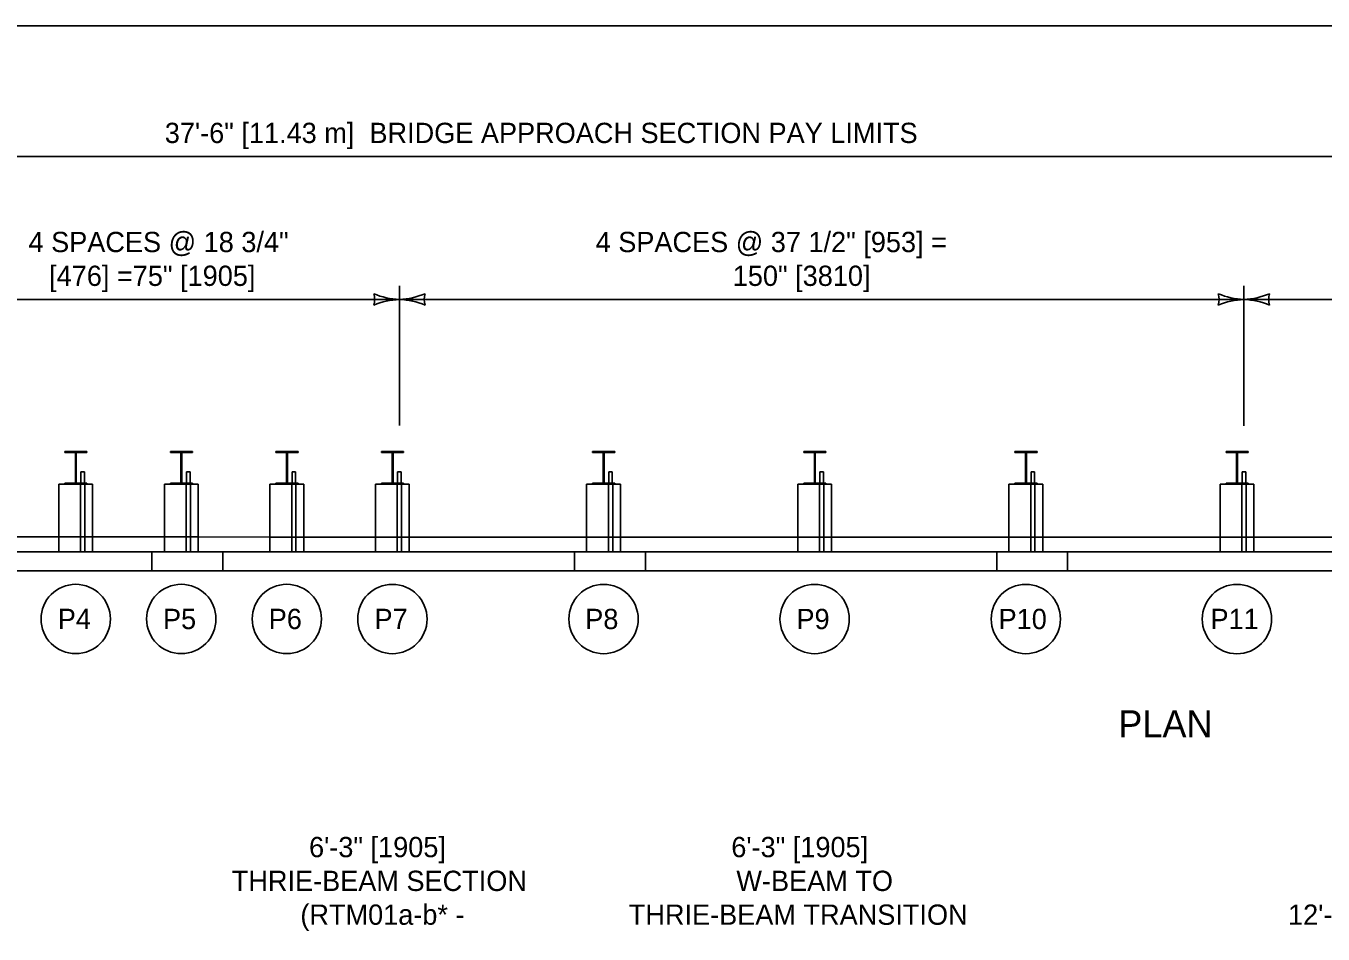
# Model space of a CAD drawing. Extents: x 49991 to 50160, y 49948 to 50051.
# Drawn here: x 50002.716 to 50006.556, y 49996.312 to 49998.999 of the extents above; entities that cross this region are included whole.
import ezdxf

# ---------------------------------------------------------------- set-up
doc = ezdxf.new("R2010")
doc.units = 0
for name, color, linetype in [('Level 1', 7, 'Continuous'), ('Level 2', 7, 'Continuous'), ('Level 3', 7, 'Continuous'), ('Level 4', 7, 'Continuous')]:
    doc.layers.add(name, color=color, linetype=linetype)

msp = doc.modelspace()

# ---------------------------------------------------------------- linework, layer by layer
at = {"layer": 'Level 1'}
for p, q in [((50002.8966, 49997.7403), (50002.831, 49997.7403)), ((50002.831, 49997.7403), (50002.831, 49997.7371)), ((50002.8966, 49997.7371), (50002.831, 49997.7371)), ((50002.8624, 49997.7371), (50002.8624, 49997.6464)), ((50002.8652, 49997.7371), (50002.8652, 49997.6464)), ((50002.8966, 49997.7371), (50002.8966, 49997.7403)), ((50003.2091, 49997.7403), (50003.1435, 49997.7403)), ((50003.1435, 49997.7403), (50003.1435, 49997.7371)), ((50003.2091, 49997.7371), (50003.1435, 49997.7371)), ((50003.1749, 49997.7371), (50003.1749, 49997.6464)), ((50003.1777, 49997.7371), (50003.1777, 49997.6464)), ((50003.2091, 49997.7371), (50003.2091, 49997.7403)), ((50003.5216, 49997.7403), (50003.456, 49997.7403)), ((50003.456, 49997.7403), (50003.456, 49997.737)), ((50003.5216, 49997.737), (50003.456, 49997.737)), ((50003.4874, 49997.737), (50003.4874, 49997.6463)), ((50003.4902, 49997.737), (50003.4902, 49997.6463)), ((50003.5216, 49997.737), (50003.5216, 49997.7403)), ((50003.8341, 49997.7403), (50003.7685, 49997.7403)), ((50003.7685, 49997.7403), (50003.7685, 49997.737)), ((50003.8341, 49997.737), (50003.7685, 49997.737)), ((50003.7999, 49997.737), (50003.7999, 49997.6463)), ((50003.8027, 49997.737), (50003.8027, 49997.6463)), ((50003.8341, 49997.737), (50003.8341, 49997.7403)), ((50004.4591, 49997.7402), (50004.3935, 49997.7402)), ((50004.3935, 49997.7402), (50004.3935, 49997.737)), ((50004.4591, 49997.737), (50004.3935, 49997.737)), ((50004.4249, 49997.737), (50004.4249, 49997.6463)), ((50004.4277, 49997.737), (50004.4277, 49997.6463)), ((50004.4591, 49997.737), (50004.4591, 49997.7402)), ((50005.0841, 49997.7402), (50005.0185, 49997.7402)), ((50005.0185, 49997.7402), (50005.0185, 49997.737)), ((50005.0841, 49997.737), (50005.0185, 49997.737)), ((50005.0499, 49997.737), (50005.0499, 49997.6463)), ((50005.0527, 49997.737), (50005.0527, 49997.6463)), ((50005.0841, 49997.737), (50005.0841, 49997.7402)), ((50005.7091, 49997.7402), (50005.6435, 49997.7402)), ((50005.6435, 49997.7402), (50005.6435, 49997.737)), ((50005.7091, 49997.737), (50005.6435, 49997.737)), ((50005.6749, 49997.737), (50005.6749, 49997.6463)), ((50005.6777, 49997.737), (50005.6777, 49997.6463)), ((50005.7091, 49997.737), (50005.7091, 49997.7402)), ((50006.3341, 49997.7402), (50006.2685, 49997.7402)), ((50006.2685, 49997.7402), (50006.2685, 49997.7369)), ((50006.3341, 49997.7369), (50006.2685, 49997.7369)), ((50006.2999, 49997.7369), (50006.2999, 49997.6462)), ((50006.3027, 49997.7369), (50006.3027, 49997.6462)), ((50006.3341, 49997.7369), (50006.3341, 49997.7402)), ((50002.8789, 49997.6797), (50002.8894, 49997.6797)), ((50002.8789, 49997.6464), (50002.8789, 49997.6797)), ((50002.8894, 49997.6464), (50002.8894, 49997.6797)), ((50003.1914, 49997.6797), (50003.2019, 49997.6797)), ((50003.1914, 49997.6464), (50003.1914, 49997.6797)), ((50003.2019, 49997.6464), (50003.2019, 49997.6797)), ((50003.5039, 49997.6797), (50003.5144, 49997.6797)), ((50003.5039, 49997.6463), (50003.5039, 49997.6797)), ((50003.5144, 49997.6463), (50003.5144, 49997.6797)), ((50003.8164, 49997.6797), (50003.8269, 49997.6797)), ((50003.8164, 49997.6463), (50003.8164, 49997.6797)), ((50003.8269, 49997.6463), (50003.8269, 49997.6797)), ((50004.4414, 49997.6796), (50004.4519, 49997.6796)), ((50004.4414, 49997.6463), (50004.4414, 49997.6796)), ((50004.4519, 49997.6463), (50004.4519, 49997.6796)), ((50005.0664, 49997.6796), (50005.0769, 49997.6796)), ((50005.0664, 49997.6463), (50005.0664, 49997.6796)), ((50005.0769, 49997.6463), (50005.0769, 49997.6796)), ((50005.6914, 49997.6796), (50005.7019, 49997.6796)), ((50005.6914, 49997.6463), (50005.6914, 49997.6796)), ((50005.7019, 49997.6463), (50005.7019, 49997.6796)), ((50006.3164, 49997.6796), (50006.3269, 49997.6796)), ((50006.3164, 49997.6462), (50006.3164, 49997.6796)), ((50006.3269, 49997.6462), (50006.3269, 49997.6796)), ((50002.8133, 49997.6431), (50002.8133, 49997.4431)), ((50002.9133, 49997.6431), (50002.8133, 49997.6431)), ((50002.831, 49997.6431), (50002.831, 49997.6464)), ((50002.831, 49997.6464), (50002.8966, 49997.6464)), ((50002.831, 49997.6431), (50002.8966, 49997.6431)), ((50002.8966, 49997.6464), (50002.8966, 49997.6431)), ((50002.9133, 49997.4431), (50002.9133, 49997.6431)), ((50003.1258, 49997.6431), (50003.1258, 49997.4431)), ((50003.2258, 49997.6431), (50003.1258, 49997.6431)), ((50003.1435, 49997.6431), (50003.1435, 49997.6464)), ((50003.1435, 49997.6464), (50003.2091, 49997.6464)), ((50003.1435, 49997.6431), (50003.2091, 49997.6431)), ((50003.2091, 49997.6464), (50003.2091, 49997.6431)), ((50003.2258, 49997.4431), (50003.2258, 49997.6431)), ((50003.4383, 49997.6431), (50003.4383, 49997.4431)), ((50003.5383, 49997.6431), (50003.4383, 49997.6431)), ((50003.456, 49997.6431), (50003.456, 49997.6463)), ((50003.456, 49997.6463), (50003.5216, 49997.6463)), ((50003.456, 49997.6431), (50003.5216, 49997.6431)), ((50003.5216, 49997.6463), (50003.5216, 49997.6431)), ((50003.5383, 49997.4431), (50003.5383, 49997.6431)), ((50003.7508, 49997.6431), (50003.7508, 49997.4431)), ((50003.8508, 49997.6431), (50003.7508, 49997.6431)), ((50003.7685, 49997.6431), (50003.7685, 49997.6463)), ((50003.7685, 49997.6463), (50003.8341, 49997.6463)), ((50003.7685, 49997.6431), (50003.8341, 49997.6431)), ((50003.8341, 49997.6463), (50003.8341, 49997.6431)), ((50003.8508, 49997.4431), (50003.8508, 49997.6431)), ((50004.3758, 49997.6431), (50004.3758, 49997.4431)), ((50004.4758, 49997.6431), (50004.3758, 49997.6431)), ((50004.3935, 49997.6431), (50004.3935, 49997.6463)), ((50004.3935, 49997.6463), (50004.4591, 49997.6463)), ((50004.3935, 49997.6431), (50004.4591, 49997.6431)), ((50004.4591, 49997.6463), (50004.4591, 49997.6431)), ((50004.4758, 49997.4431), (50004.4758, 49997.6431)), ((50005.0008, 49997.643), (50005.0008, 49997.443)), ((50005.1008, 49997.643), (50005.0008, 49997.643)), ((50005.0185, 49997.643), (50005.0185, 49997.6463)), ((50005.0185, 49997.6463), (50005.0841, 49997.6463)), ((50005.0185, 49997.643), (50005.0841, 49997.643)), ((50005.0841, 49997.6463), (50005.0841, 49997.643)), ((50005.1008, 49997.443), (50005.1008, 49997.643)), ((50005.6258, 49997.643), (50005.6258, 49997.443)), ((50005.7258, 49997.643), (50005.6258, 49997.643)), ((50005.6435, 49997.643), (50005.6435, 49997.6463)), ((50005.6435, 49997.6463), (50005.7091, 49997.6463)), ((50005.6435, 49997.643), (50005.7091, 49997.643)), ((50005.7091, 49997.6463), (50005.7091, 49997.643)), ((50005.7258, 49997.443), (50005.7258, 49997.643)), ((50006.2508, 49997.643), (50006.2508, 49997.443)), ((50006.3508, 49997.643), (50006.2508, 49997.643)), ((50006.2685, 49997.643), (50006.2685, 49997.6462)), ((50006.2685, 49997.6462), (50006.3341, 49997.6462)), ((50006.2685, 49997.643), (50006.3341, 49997.643)), ((50006.3341, 49997.6462), (50006.3341, 49997.643)), ((50006.3508, 49997.443), (50006.3508, 49997.643)), ((50002.6008, 49997.487), (50002.8133, 49997.487)), ((50002.9133, 49997.487), (50003.1258, 49997.487)), ((50003.2258, 49997.487), (50003.4383, 49997.4869)), ((50003.5383, 49997.4869), (50003.7508, 49997.4869)), ((50003.8508, 49997.4869), (50004.3758, 49997.4869)), ((50004.4758, 49997.4869), (50005.0008, 49997.4869)), ((50005.1008, 49997.4869), (50005.6258, 49997.4869)), ((50005.7258, 49997.4869), (50006.2508, 49997.4869)), ((50006.3508, 49997.4869), (50007.5008, 49997.4869)), ((49999.8238, 49997.4433), (50011.6716, 49997.4428)), ((50002.9133, 49997.4431), (50002.8133, 49997.4431)), ((50003.0886, 49997.3869), (50003.0886, 49997.4431)), ((50003.2258, 49997.4431), (50003.1258, 49997.4431)), ((50003.5383, 49997.4431), (50003.4383, 49997.4431)), ((50003.8508, 49997.4431), (50003.7508, 49997.4431)), ((50004.3397, 49997.3869), (50004.3397, 49997.4431)), ((50004.4758, 49997.4431), (50004.3758, 49997.4431)), ((50005.1008, 49997.443), (50005.0008, 49997.443)), ((50005.5897, 49997.3868), (50005.5897, 49997.443)), ((50005.7258, 49997.443), (50005.6258, 49997.443)), ((50006.3508, 49997.443), (50006.2508, 49997.443)), ((49999.8238, 49997.387), (50011.6716, 49997.3866))]:
    msp.add_line(p, q, dxfattribs=at)
msp.add_lwpolyline([(49999.3835, 49998.9992), (50016.7501, 49998.9992), (50016.7501, 49987.7988), (49999.3835, 49987.7988)], close=True, dxfattribs=at)
at = {"layer": 'Level 2'}
for centre in [(50002.8634, 49997.2443), (50003.1759, 49997.2443), (50003.4883, 49997.2443), (50003.8008, 49997.2442), (50004.4259, 49997.2442), (50005.0508, 49997.2442), (50005.6759, 49997.2442), (50006.3009, 49997.2441)]:
    msp.add_circle(centre, 0.1026, dxfattribs=at)
at = {"layer": 'Level 3'}
for p, q in [((50000.6957, 49998.6127), (50008.1966, 49998.6127)), ((50003.8216, 49997.8164), (50003.8216, 49998.2299)), ((50006.3216, 49997.8163), (50006.3216, 49998.2299)), ((50002.5716, 49998.1899), (50003.8216, 49998.1899)), ((50003.8216, 49998.1899), (50006.3216, 49998.1899)), ((50006.3216, 49998.1899), (50011.5324, 49998.1899)), ((50002.8841, 49997.3868), (50002.5716, 49997.3868)), ((50003.1966, 49997.3868), (50002.8841, 49997.3868)), ((50003.5091, 49997.3868), (50003.1966, 49997.3868)), ((50003.8216, 49997.3868), (50003.5091, 49997.3868)), ((50004.4466, 49997.3868), (50003.8216, 49997.3868)), ((50005.0716, 49997.3868), (50004.4466, 49997.3868)), ((50005.6966, 49997.3868), (50005.0716, 49997.3868)), ((50006.3216, 49997.3868), (50005.6966, 49997.3868)), ((50007.5716, 49997.3868), (50006.3216, 49997.3868))]:
    msp.add_line(p, q, dxfattribs=at)
for centre, radius, start, end in [((50003.8308, 49998.412), 0.2223, 247.456, 267.6395), ((50003.6934, 49998.1899), 0.0548, 342.1388, 17.8612), ((50003.8102, 49998.4226), 0.233, 272.8273, 292.0772), ((50003.9499, 49998.1899), 0.0548, 162.1388, 197.8612), ((50006.3308, 49998.412), 0.2223, 247.456, 267.6395), ((50006.1934, 49998.1899), 0.0548, 342.1388, 17.8612), ((50006.3102, 49998.4226), 0.233, 272.8273, 292.0772), ((50006.4499, 49998.1899), 0.0548, 162.1388, 197.8612), ((50003.8331, 49997.9572), 0.233, 92.8273, 112.0772), ((50003.8125, 49997.9678), 0.2223, 67.456, 87.6395), ((50006.3331, 49997.9572), 0.233, 92.8273, 112.0772), ((50006.3125, 49997.9678), 0.2223, 67.456, 87.6395)]:
    msp.add_arc(centre, radius, start, end, dxfattribs=at)
at = {"layer": 'Level 4'}
for p, q in [((50002.8779, 49997.4431), (50002.8779, 49997.6431)), ((50002.8904, 49997.4431), (50002.8904, 49997.6431)), ((50003.1904, 49997.4431), (50003.1904, 49997.6431)), ((50003.2029, 49997.4431), (50003.2029, 49997.6431)), ((50003.5029, 49997.4431), (50003.5029, 49997.6431)), ((50003.5154, 49997.4431), (50003.5154, 49997.6431)), ((50003.8154, 49997.4431), (50003.8154, 49997.6431)), ((50003.8279, 49997.4431), (50003.8279, 49997.6431)), ((50004.4404, 49997.4431), (50004.4404, 49997.6431)), ((50004.4529, 49997.4431), (50004.4529, 49997.6431)), ((50005.0654, 49997.443), (50005.0654, 49997.643)), ((50005.0779, 49997.443), (50005.0779, 49997.643)), ((50005.6904, 49997.443), (50005.6904, 49997.643)), ((50005.7029, 49997.443), (50005.7029, 49997.643)), ((50006.3154, 49997.443), (50006.3154, 49997.643)), ((50006.3279, 49997.443), (50006.3279, 49997.643)), ((50002.8133, 49997.487), (50002.9133, 49997.487)), ((50003.1258, 49997.487), (50003.2258, 49997.487)), ((50003.4383, 49997.4869), (50003.5383, 49997.4869)), ((50003.7508, 49997.4869), (50003.8508, 49997.4869)), ((50004.3758, 49997.4869), (50004.4758, 49997.4869)), ((50005.0008, 49997.4869), (50005.1008, 49997.4869)), ((50005.6258, 49997.4869), (50005.7258, 49997.4869)), ((50006.2508, 49997.4869), (50006.3508, 49997.4869)), ((50003.2985, 49997.3868), (50003.2985, 49997.4431)), ((50004.5497, 49997.3869), (50004.5497, 49997.4431)), ((50005.7997, 49997.3868), (50005.7997, 49997.443))]:
    msp.add_line(p, q, dxfattribs=at)

# ---------------------------------------------------------------- texts
at = {"layer": 'Level 2'}
for s, height, p in [('37\'-6" [11.43 m]  BRIDGE APPROACH SECTION PAY LIMITS', 0.06, (50003.1271, 49998.6527)), ('4 SPACES @ 18 3/4"', 0.06, (50002.7237, 49998.3299)), ('4 SPACES @ 37 1/2" [953] =', 0.06, (50004.4025, 49998.3299)), (' [476] =75" [1905]', 0.06, (50002.7624, 49998.2299)), ('150" [3810]', 0.06, (50004.8084, 49998.2299)), ('P4', 0.06, (50002.8103, 49997.2146)), ('P5', 0.06, (50003.1217, 49997.2144)), ('P6', 0.06, (50003.4347, 49997.2145)), ('P7', 0.06, (50003.7478, 49997.2145)), ('P8', 0.06, (50004.3717, 49997.2144)), ('P9', 0.06, (50004.997, 49997.2143)), ('P10', 0.06, (50005.5953, 49997.2143)), ('P11', 0.06, (50006.2226, 49997.2144)), ('PLAN', 0.08, (50005.9494, 49996.894)), ('6\'-3" [1905] ', 0.06, (50003.5541, 49996.5394)), ('6\'-3" [1905] ', 0.06, (50004.8041, 49996.5394)), ('THRIE-BEAM SECTION', 0.06, (50003.3254, 49996.4394)), ('W-BEAM TO', 0.06, (50004.8191, 49996.4394)), ('(RTM01a-b* -', 0.06, (50003.5284, 49996.3394)), ('THRIE-BEAM TRANSITION', 0.06, (50004.5007, 49996.3394)), ('12\'-6" [3810] W-BEAM', 0.06, (50006.4522, 49996.3394))]:
    msp.add_text(s, height=height, dxfattribs=at).set_placement(p)

doc.saveas('drawing.dxf')
